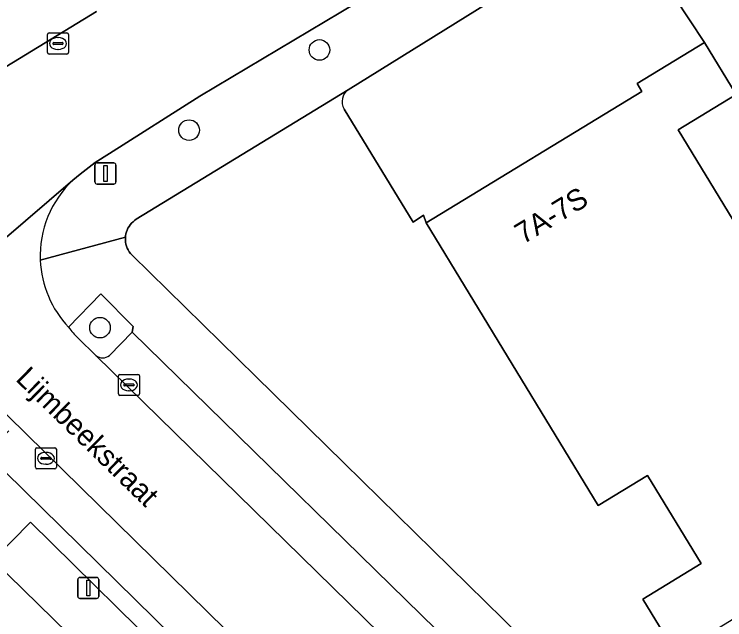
# Model space of a CAD drawing. Extents: x 159888 to 160761, y 384031 to 384750.
# Drawn here: x 160203.84 to 160237.54, y 384505.51 to 384534.23 of the extents above; entities that cross this region are included whole.
import ezdxf

# ---------------------------------------------------------------- set-up
doc = ezdxf.new("R2010")
doc.units = 0
for name, color, linetype in [('IMGEO_Boom', 7, 'Continuous'), ('IMGEO_Erf', 7, 'Continuous'), ('IMGEO_Groenvoorziening', 7, 'Continuous'), ('IMGEO_Kolk', 7, 'Continuous'), ('IMGEO_Lichtmast', 7, 'Continuous'), ('IMGEO_Openbare_ruimte_label', 7, 'Continuous'), ('IMGEO_Pand', 7, 'Continuous'), ('IMGEO_Pand_nummerreeks', 7, 'Continuous'), ('IMGEO_Parkeervlak_open', 7, 'Continuous'), ('IMGEO_Rijbaan_lokaal_open', 7, 'Continuous'), ('IMGEO_Voetpad_open', 7, 'Continuous')]:
    doc.layers.add(name, color=color, linetype=linetype)

msp = doc.modelspace()

# ---------------------------------------------------------------- linework, layer by layer
at = {"layer": 'IMGEO_Boom'}
for centre in [(160218.315, 384532.537), (160212.131, 384528.734), (160207.907, 384519.367)]:
    msp.add_circle(centre, 0.489, dxfattribs=at)
at = {"layer": 'IMGEO_Erf'}
for points in [[(160268.727, 384561.037), (160236.781, 384541.5), (160236.88, 384541.336), (160232.217, 384538.441), (160232.643, 384538.485), (160233.023, 384538.287), (160236.574, 384532.884), (160238.073, 384530.42), (160235.324, 384528.748), (160237.931, 384524.463), (160240.21, 384525.85), (160248.414, 384512.365), (160251.931, 384506.246)], [(160219.671, 384530.65), (160209.63, 384524.507), (160209.549, 384524.452), (160209.474, 384524.391), (160209.404, 384524.323), (160209.34, 384524.248), (160209.284, 384524.169), (160209.235, 384524.085), (160209.193, 384523.997), (160209.16, 384523.905), (160209.134, 384523.811), (160209.118, 384523.715), (160209.114, 384523.662), (160209.11, 384523.617), (160209.111, 384523.52), (160209.12, 384523.423), (160209.138, 384523.327), (160209.165, 384523.233), (160209.199, 384523.142), (160209.242, 384523.054), (160209.293, 384522.971), (160209.351, 384522.892), (160209.415, 384522.819), (160209.436, 384522.798), (160231.216, 384501.429)], [(160223.372, 384524.341), (160223.248, 384524.697), (160222.753, 384524.374), (160219.489, 384529.735)], [(160235.233, 384503.903), (160233.656, 384506.495), (160236.417, 384508.175), (160233.87, 384512.362), (160231.527, 384510.936), (160223.372, 384524.341)]]:
    msp.add_lwpolyline(points, dxfattribs=at)
msp.add_arc((160220.079, 384530.093), 0.69, 126.2272, 211.2734, dxfattribs=at)
at = {"layer": 'IMGEO_Groenvoorziening'}
for points in [[(160208.357, 384518.044), (160209.434, 384519.16), (160209.478, 384519.428), (160207.949, 384520.971), (160206.42, 384519.384)], [(160206.869, 384518.871), (160207.717, 384518.046)]]:
    msp.add_lwpolyline(points, dxfattribs=at)
msp.add_lwpolyline([(160204.606, 384510.136), (160202.83, 384508.346), (160209.967, 384501.371), (160211.746, 384503.128)], close=True, dxfattribs=at)
for centre, radius, start, end in [((160209.484, 384521.613), 3.789, 216.0324, 226.3553), ((160208.038, 384518.449), 0.515, 231.4088, 308.2331)]:
    msp.add_arc(centre, radius, start, end, dxfattribs=at)
at = {"layer": 'IMGEO_Kolk'}
for p, q in [((160205.49, 384533.343), (160206.342, 384533.343)), ((160205.415, 384532.417), (160205.415, 384533.269)), ((160205.903, 384533.123), (160205.928, 384533.123)), ((160206.416, 384533.269), (160206.416, 384532.417)), ((160205.674, 384532.837), (160205.674, 384532.849)), ((160206.112, 384532.8), (160205.714, 384532.8)), ((160205.717, 384532.886), (160206.115, 384532.886)), ((160206.158, 384532.849), (160206.158, 384532.837)), ((160206.342, 384532.343), (160205.49, 384532.343)), ((160205.926, 384532.563), (160205.901, 384532.563)), ((160208.855, 384517.152), (160209.707, 384517.152)), ((160208.78, 384516.226), (160208.78, 384517.078)), ((160209.268, 384516.932), (160209.293, 384516.932)), ((160209.781, 384517.078), (160209.781, 384516.226)), ((160209.039, 384516.646), (160209.039, 384516.658)), ((160209.477, 384516.609), (160209.079, 384516.609)), ((160209.082, 384516.695), (160209.48, 384516.695)), ((160209.523, 384516.658), (160209.523, 384516.646)), ((160209.707, 384516.152), (160208.855, 384516.152)), ((160209.291, 384516.372), (160209.266, 384516.372)), ((160204.841, 384512.745), (160204.841, 384513.597)), ((160204.916, 384513.671), (160205.768, 384513.671)), ((160205.329, 384513.451), (160205.354, 384513.451)), ((160205.842, 384513.597), (160205.842, 384512.745)), ((160205.1, 384513.165), (160205.1, 384513.177)), ((160205.538, 384513.128), (160205.14, 384513.128)), ((160205.143, 384513.214), (160205.541, 384513.214)), ((160205.584, 384513.177), (160205.584, 384513.165)), ((160205.352, 384512.891), (160205.327, 384512.891)), ((160205.768, 384512.671), (160204.916, 384512.671))]:
    msp.add_line(p, q, dxfattribs=at)
for points in [[(160205.49, 384533.343), (160206.342, 384533.343)], [(160205.415, 384532.417), (160205.415, 384533.269)], [(160206.416, 384533.269), (160206.416, 384532.417)], [(160206.342, 384532.343), (160205.49, 384532.343)], [(160208.855, 384517.152), (160209.707, 384517.152)], [(160208.78, 384516.226), (160208.78, 384517.078)], [(160209.781, 384517.078), (160209.781, 384516.226)], [(160209.707, 384516.152), (160208.855, 384516.152)], [(160204.841, 384512.745), (160204.841, 384513.597)], [(160204.916, 384513.671), (160205.768, 384513.671)], [(160205.842, 384513.597), (160205.842, 384512.745)], [(160205.768, 384512.671), (160204.916, 384512.671)]]:
    msp.add_lwpolyline(points, dxfattribs=at)
for centre, radius, start, end in [((160205.492, 384533.267), 0.0765, 91.552, 178.448), ((160205.492, 384533.267), 0.0765, 91.552, 178.448), ((160206.34, 384533.267), 0.0765, 1.552, 88.448), ((160206.34, 384533.267), 0.0765, 1.552, 88.448), ((160205.714, 384532.846), 0.0403, 85.8775, 175.7526), ((160205.711, 384532.836), 0.0366, 178.938, 274.7102), ((160206.115, 384532.843), 0.043, 264.8664, 352.4533), ((160206.119, 384532.848), 0.0386, 1.7309, 96.639), ((160205.492, 384532.419), 0.0765, 181.552, 268.448), ((160205.492, 384532.419), 0.0765, 181.552, 268.448), ((160206.34, 384532.419), 0.0765, 271.552, 358.448), ((160206.34, 384532.419), 0.0765, 271.552, 358.448), ((160208.857, 384517.076), 0.0765, 91.552, 178.448), ((160208.857, 384517.076), 0.0765, 91.552, 178.448), ((160209.705, 384517.076), 0.0765, 1.552, 88.448), ((160209.705, 384517.076), 0.0765, 1.552, 88.448), ((160209.079, 384516.655), 0.0403, 85.8775, 175.7526), ((160209.076, 384516.645), 0.0366, 178.938, 274.7102), ((160209.48, 384516.652), 0.043, 264.8664, 352.4533), ((160209.484, 384516.657), 0.0386, 1.7309, 96.639), ((160208.857, 384516.228), 0.0765, 181.552, 268.448), ((160208.857, 384516.228), 0.0765, 181.552, 268.448), ((160209.705, 384516.228), 0.0765, 271.552, 358.448), ((160209.705, 384516.228), 0.0765, 271.552, 358.448), ((160204.918, 384513.595), 0.0765, 91.552, 178.448), ((160204.918, 384513.595), 0.0765, 91.552, 178.448), ((160205.766, 384513.595), 0.0765, 1.552, 88.448), ((160205.766, 384513.595), 0.0765, 1.552, 88.448), ((160205.14, 384513.174), 0.0403, 85.8775, 175.7526), ((160205.137, 384513.164), 0.0366, 178.938, 274.7102), ((160205.541, 384513.171), 0.043, 264.8664, 352.4533), ((160205.545, 384513.176), 0.0386, 1.7309, 96.639), ((160204.918, 384512.747), 0.0765, 181.552, 268.448), ((160204.918, 384512.747), 0.0765, 181.552, 268.448), ((160205.766, 384512.747), 0.0765, 271.552, 358.448), ((160205.766, 384512.747), 0.0765, 271.552, 358.448)]:
    msp.add_arc(centre, radius, start, end, dxfattribs=at)
for centre, major_axis, ratio, start_param, end_param in [((160205.902, 384532.843), (-0.387, 0.002), 0.722429, 4.712389, 7.853982), ((160205.927, 384532.843), (-0.39, 0.002), 0.717154, 1.570796, 4.712389), ((160209.267, 384516.652), (-0.387, 0.002), 0.722429, 4.712389, 7.853982), ((160209.292, 384516.652), (-0.39, 0.002), 0.717154, 1.570796, 4.712389), ((160205.328, 384513.171), (-0.387, 0.002), 0.722429, 4.712389, 7.853982), ((160205.353, 384513.171), (-0.39, 0.002), 0.717154, 1.570796, 4.712389)]:
    msp.add_ellipse(centre, major_axis=major_axis, ratio=ratio, start_param=start_param, end_param=end_param, dxfattribs=at)
at = {"layer": 'IMGEO_Lichtmast'}
for p, q in [((160207.67, 384526.28), (160207.67, 384527.08)), ((160207.67, 384527.08), (160207.67, 384526.28)), ((160207.77, 384527.18), (160208.56, 384527.18)), ((160208.56, 384527.18), (160207.77, 384527.18)), ((160208.66, 384527.08), (160208.66, 384526.28)), ((160208.66, 384526.28), (160208.66, 384527.08)), ((160208.56, 384526.18), (160207.77, 384526.18)), ((160207.77, 384526.18), (160208.56, 384526.18)), ((160206.856, 384506.622), (160206.856, 384507.422)), ((160206.856, 384507.422), (160206.856, 384506.622)), ((160206.956, 384507.522), (160207.746, 384507.522)), ((160207.746, 384507.522), (160206.956, 384507.522)), ((160207.846, 384507.422), (160207.846, 384506.622)), ((160207.846, 384506.622), (160207.846, 384507.422)), ((160207.746, 384506.522), (160206.956, 384506.522)), ((160206.956, 384506.522), (160207.746, 384506.522))]:
    msp.add_line(p, q, dxfattribs=at)
for points in [[(160208.09, 384527.055), (160208.24, 384527.055), (160208.24, 384526.305), (160208.09, 384526.305), (160208.09, 384527.055)], [(160207.276, 384507.397), (160207.426, 384507.397), (160207.426, 384506.647), (160207.276, 384506.647), (160207.276, 384507.397)]]:
    msp.add_lwpolyline(points, dxfattribs=at)
for centre, start, end in [((160207.77, 384527.08), 90, 180), ((160207.77, 384527.08), 90, 180), ((160208.56, 384527.08), 0, 90), ((160208.56, 384527.08), 360, 90), ((160207.77, 384526.28), 180, 270), ((160207.77, 384526.28), 180, 270), ((160208.56, 384526.28), 270, 0), ((160208.56, 384526.28), 270, 0), ((160206.956, 384507.422), 90, 180), ((160206.956, 384507.422), 90, 180), ((160207.746, 384507.422), 0, 90), ((160207.746, 384507.422), 360, 90), ((160206.956, 384506.622), 180, 270), ((160206.956, 384506.622), 180, 270), ((160207.746, 384506.622), 270, 0), ((160207.746, 384506.622), 270, 0)]:
    msp.add_arc(centre, 0.1, start, end, dxfattribs=at)
at = {"layer": 'IMGEO_Pand'}
msp.add_lwpolyline([(160235.233, 384503.903), (160238.466, 384505.869), (160238.269, 384506.193), (160248.414, 384512.365), (160240.21, 384525.85), (160237.931, 384524.463), (160235.324, 384528.748), (160238.073, 384530.42), (160236.574, 384532.884), (160233.385, 384530.944), (160233.612, 384530.57), (160223.372, 384524.341), (160231.527, 384510.936), (160233.87, 384512.362), (160236.417, 384508.175), (160233.656, 384506.495)], close=True, dxfattribs=at)
at = {"layer": 'IMGEO_Parkeervlak_open'}
for points in [[(160219.489, 384529.735), (160222.753, 384524.374), (160223.248, 384524.697), (160223.372, 384524.341), (160233.612, 384530.57), (160233.385, 384530.944), (160236.574, 384532.884), (160233.023, 384538.287), (160232.643, 384538.485), (160232.217, 384538.441), (160229.051, 384536.475), (160226.272, 384534.749), (160219.671, 384530.65)], [(160202.207, 384530.993), (160207.734, 384534.361)], [(160209.434, 384519.16), (160208.357, 384518.044)], [(160224.91, 384501.836), (160226.022, 384502.938), (160209.434, 384519.16)], [(160207.717, 384518.046), (160224.94, 384501.185)], [(160234.606, 384485.229), (160232.947, 384486.549), (160231.049, 384488.176), (160203.557, 384515.169)], [(160203.589, 384514.481), (160202.511, 384513.401), (160229.885, 384486.517), (160231.834, 384484.894), (160233.589, 384483.523)]]:
    msp.add_lwpolyline(points, dxfattribs=at)
for centre, radius, start, end in [((160220.079, 384530.093), 0.69, 126.2272, 211.2734), ((160208.038, 384518.449), 0.515, 231.4088, 308.2331)]:
    msp.add_arc(centre, radius, start, end, dxfattribs=at)
at = {"layer": 'IMGEO_Rijbaan_lokaal_open'}
for points in [[(160184.709, 384510.733), (160189.233, 384513.236), (160194.348, 384516.163), (160195.384, 384516.714), (160206.625, 384526.362), (160206.965, 384526.653), (160207.672, 384527.208), (160208.363, 384527.623), (160212.649, 384530.34), (160222.306, 384536.124)], [(160207.734, 384534.361), (160202.207, 384530.993), (160200.674, 384530.059), (160191.357, 384524.402), (160190.091, 384523.634), (160180.747, 384517.987)], [(160206.625, 384526.362), (160195.384, 384516.714)], [(160207.717, 384518.046), (160206.869, 384518.871)], [(160236.102, 384490.375), (160234.472, 384491.786), (160233.004, 384493.205), (160226.392, 384499.753), (160224.94, 384501.185), (160207.717, 384518.046)], [(160202.743, 384515.892), (160203.557, 384515.169), (160231.049, 384488.176), (160232.947, 384486.549), (160234.606, 384485.229)]]:
    msp.add_lwpolyline(points, dxfattribs=at)
for centre, radius, start, end in [((160210.007, 384522.769), 4.935, 133.2708, 182.3581), ((160210.009, 384522.773), 4.936, 182.4052, 223.3603), ((160209.484, 384521.613), 3.789, 216.0324, 226.3553)]:
    msp.add_arc(centre, radius, start, end, dxfattribs=at)
at = {"layer": 'IMGEO_Voetpad_open'}
for points in [[(160219.671, 384530.65), (160226.272, 384534.749), (160224.577, 384537.511), (160222.306, 384536.124), (160212.649, 384530.34), (160208.363, 384527.623), (160207.672, 384527.208), (160206.965, 384526.653), (160206.625, 384526.362)], [(160205.077, 384522.566), (160209.114, 384523.662), (160209.118, 384523.715), (160209.134, 384523.811), (160209.16, 384523.905), (160209.193, 384523.997), (160209.235, 384524.085), (160209.284, 384524.169), (160209.34, 384524.248), (160209.404, 384524.323), (160209.474, 384524.391), (160209.549, 384524.452), (160209.63, 384524.507), (160219.671, 384530.65)], [(160240.701, 384492.09), (160234.712, 384497.923), (160232.647, 384500), (160231.216, 384501.429), (160209.436, 384522.798), (160209.415, 384522.819), (160209.351, 384522.892), (160209.293, 384522.971), (160209.242, 384523.054), (160209.199, 384523.142), (160209.165, 384523.233), (160209.138, 384523.327), (160209.12, 384523.423), (160209.111, 384523.52), (160209.11, 384523.617), (160209.114, 384523.662), (160205.077, 384522.566)], [(160206.42, 384519.384), (160207.949, 384520.971), (160209.478, 384519.428), (160209.434, 384519.16), (160226.022, 384502.938), (160226.336, 384502.94), (160227.966, 384501.332), (160226.392, 384499.753), (160233.004, 384493.205), (160234.638, 384494.783), (160236.135, 384493.293), (160236.194, 384492.935), (160238.371, 384491.083)], [(160233.589, 384483.523), (160231.834, 384484.894), (160229.885, 384486.517), (160202.511, 384513.401), (160203.589, 384514.481)]]:
    msp.add_lwpolyline(points, dxfattribs=at)
msp.add_lwpolyline([(160204.606, 384510.136), (160211.746, 384503.128), (160209.967, 384501.371), (160202.83, 384508.346)], close=True, dxfattribs=at)
for centre, radius, start, end in [((160210.007, 384522.769), 4.935, 133.2708, 182.3581), ((160210.009, 384522.773), 4.936, 182.4052, 223.3603)]:
    msp.add_arc(centre, radius, start, end, dxfattribs=at)

# ---------------------------------------------------------------- texts
at = {"layer": 'IMGEO_Openbare_ruimte_label'}
msp.add_text('Lijmbeekstraat', height=1, rotation=315.6483, dxfattribs=at).set_placement((160203.863, 384516.889))
at = {"layer": 'IMGEO_Pand_nummerreeks'}
msp.add_text('7A-7S', height=1, rotation=31.3122, dxfattribs=at).set_placement((160227.977, 384523.304))

doc.saveas('drawing.dxf')
